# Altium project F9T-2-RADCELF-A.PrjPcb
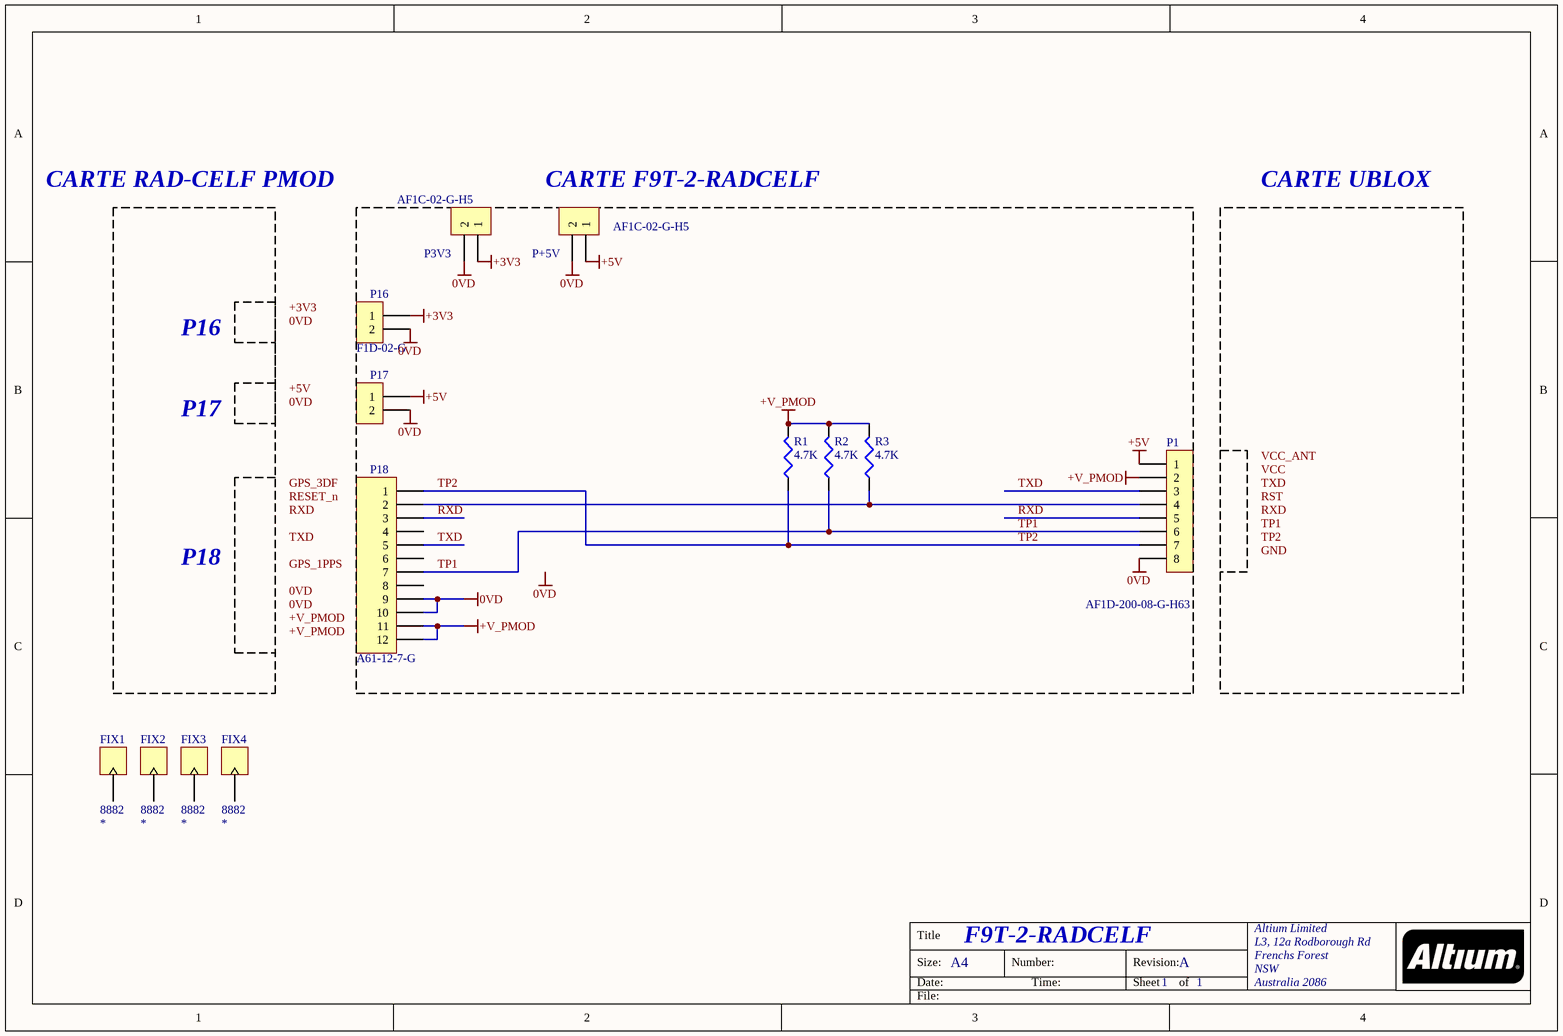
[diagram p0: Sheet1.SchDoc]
1 sheet, 13 parts. Net scope: global (net labels, ports and power ports of the same name join across sheets).
Board files: F9T-2-RADCELF-A.PcbDoc, F9T-2-RADCELF - MECA.PcbDoc

## Sheet Sheet1.SchDoc
size A4; Organization: Altium Limited; Address1: L3, 12a Rodborough Rd; Address2: Frenchs Forest; Address3: NSW; Address4: Australia 2086; Revision: A; SheetNumber: 1; SheetTotal: 1

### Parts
FIX1  8882  [8882]
FIX2  8882  [8882]
FIX3  8882  [8882]
FIX4  8882  [8882]
P1  AF1D-200-08-G-H63  [AF1D-200-08-G-H63]
P3V3  AF1C-02-G-H5  [AF1C-02-G-H5]
P16  F1D-02-G  [F1D-02-G]
P17  (no value)  [F1D-02-G]
P18  A61-12-7-G  [A61-12-7-G]
P+5V  AF1C-02-G-H5  [AF1C-02-G-H5]
R1  4.7K  [0603]
R2  4.7K  [0603]
R3  4.7K  [0603]

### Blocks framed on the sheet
CARTE F9T-2-RADCELF: P1 P3V3 P16-P18 P+5V R1-R3

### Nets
0VD: P1.8 P3V3.2 P16.2 P17.2 P18.9 P18.10 P+5V.2
+3V3: P3V3.1 P16.1
+5V: P1.1 P17.1 P+5V.1
+V_PMOD: P1.2 P18.11 P18.12 R1.2 R2.2 R3.2
RXD: P1.5 P18.3
TP1: P1.6 P18.7 R2.1
TP2: P1.7 P18.1 R1.1
TXD: P1.3 P18.5
NetP1_4: P1.4 P18.2 R3.1

Not connected (* = marked no-connect by the designer): FIX1 1; FIX2 1; FIX3 1; FIX4 1; P18 4 6 8

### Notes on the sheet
- CARTE RAD-CELF PMOD
- CARTE UBLOX
- P16
- P17
- P18
- F9T-2-RADCELF
- Labels drawn without touching a wire or pin: 0VD, +3V3, +5V, +V_PMOD, GND, GPS_1PPS, GPS_3DF, RESET_n, RST, RXD, TP1, TP2, TXD, VCC, VCC_ANT

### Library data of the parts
FIX1-FIX4 = CON1: Connector; Manufacturer 1: KEYSTONE
P1 = CON8: Connector; Manufacturer 1: ANTELEC
P3V3 P16 P17 P+5V = CON2: Connector; Manufacturer 1: ANTELEC
P18 = CON12: Connector; Manufacturer 1: ANTELEC
R1-R3 = 0805R: RES SMD 4.7K 1% 1/5W 0603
